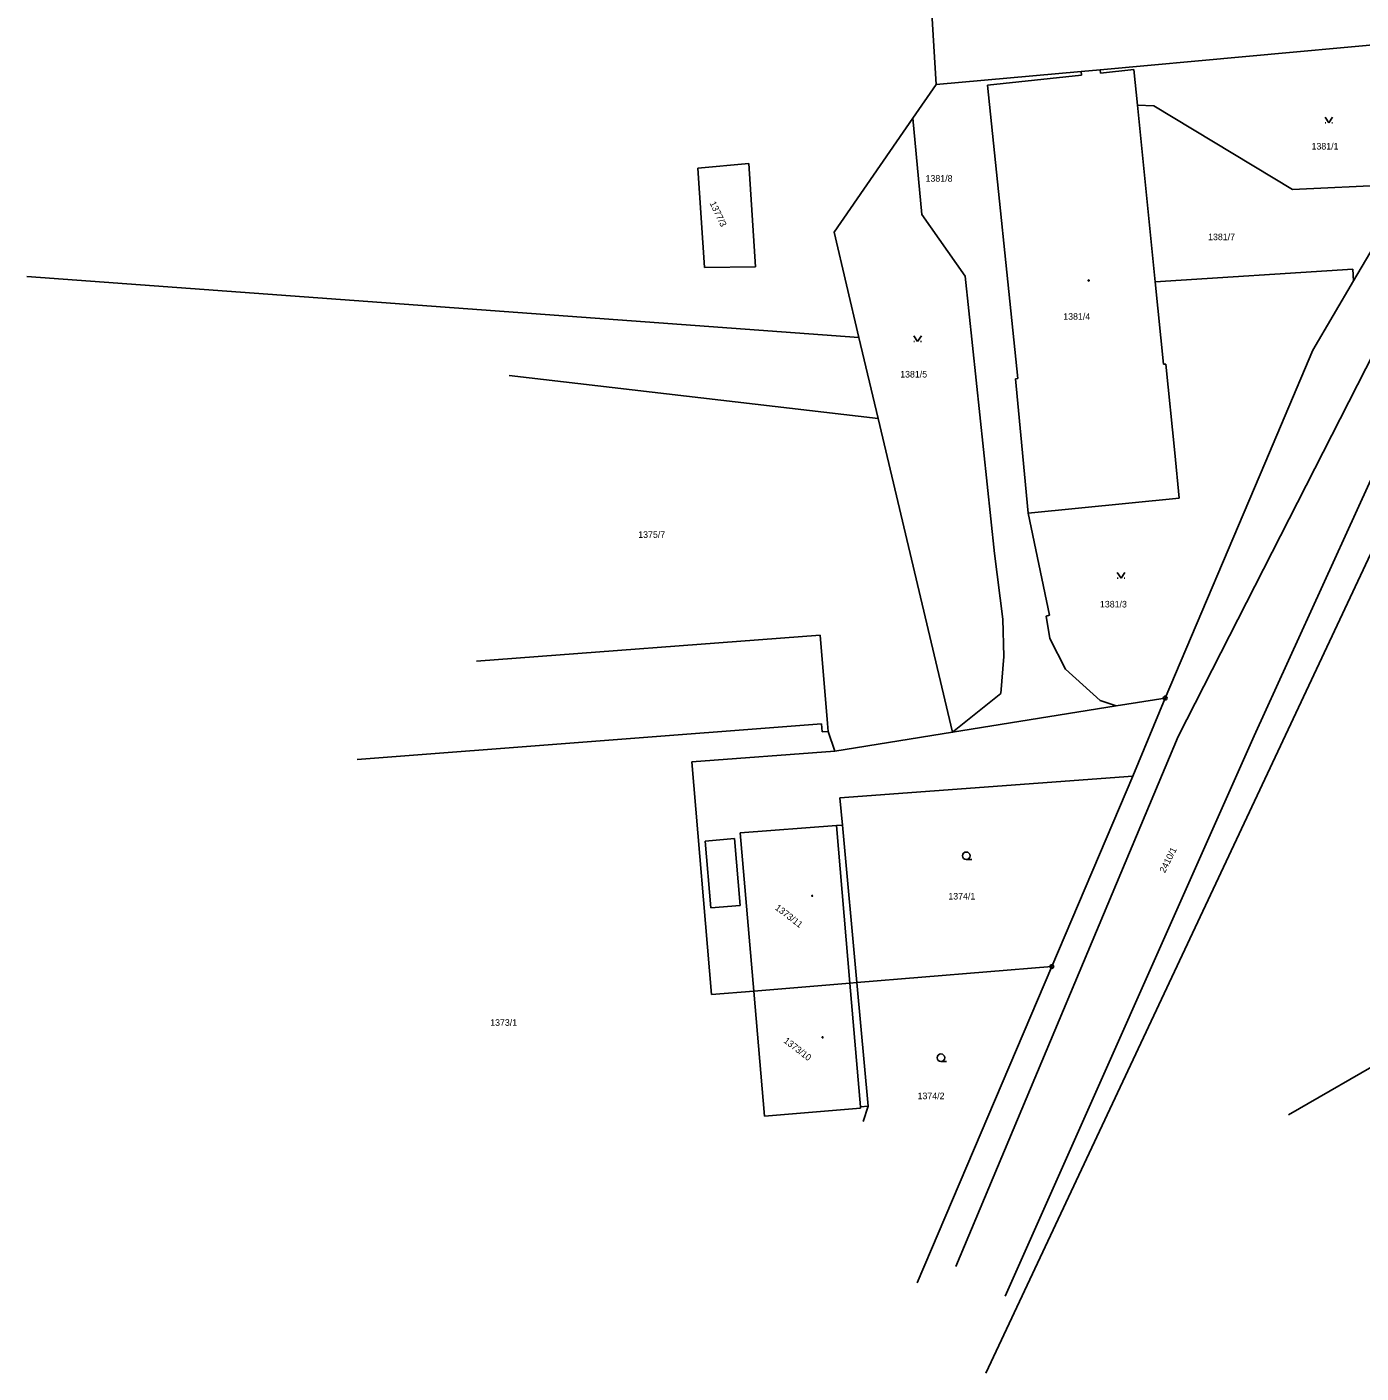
# Model space of a CAD drawing. Extents: x -454285 to -453563, y -1108687 to -1108249.
# Drawn here: x -454283.2 to -454141.3, y -1108686.8 to -1108543.6 of the extents above; entities that cross this region are included whole.
import ezdxf

# ---------------------------------------------------------------- set-up
doc = ezdxf.new("R2010")
doc.units = 0
for name, color, linetype in [('1', 7, 'Continuous'), ('14', 7, 'Continuous'), ('15', 7, 'Continuous'), ('16', 7, 'Continuous'), ('2', 7, 'Continuous'), ('23', 7, 'Continuous'), ('25', 7, 'Continuous'), ('28', 7, 'Continuous')]:
    doc.layers.add(name, color=color, linetype=linetype)

# ---------------------------------------------------------------- blocks, each defined once
blk = doc.blocks.new('Z402')
for start, end in [(0, 180), (180, 0)]:
    blk.add_arc((0, 0), 0.15, start, end)
blk = doc.blocks.new('Z105')
for radius in [0.5, 0.01]:
    blk.add_circle((0, 0), radius)
blk = doc.blocks.new('Z3140')
for p, q in [((-1, 1.5), (0, 0)), ((-1, 0), (-0.8, 0)), ((0, 0), (1, 1.5)), ((0.8, 0), (1, 0))]:
    blk.add_line(p, q)
blk = doc.blocks.new('Z3040')
blk.add_line((1.5, 0), (0, 0))
blk.add_circle((0, 1), 1)

msp = doc.modelspace()

# ---------------------------------------------------------------- linework, layer by layer
at = {"layer": '1'}
for p, q in [((-454188.53, -1108516.12), (-454186.51, -1108549.78)), ((-454169.07, -1108548.2), (-454133.68, -1108544.98)), ((-454186.51, -1108549.78), (-454171.1, -1108548.38)), ((-454181.06, -1108549.84), (-454171.06, -1108548.77)), ((-454171.1, -1108548.38), (-454169.07, -1108548.2)), ((-454171.06, -1108548.77), (-454171.1, -1108548.38)), ((-454169.07, -1108548.2), (-454169.03, -1108548.56)), ((-454169.03, -1108548.56), (-454165.48, -1108548.18)), ((-454165.48, -1108548.18), (-454165.1, -1108551.96)), ((-454188.97, -1108553.33), (-454186.51, -1108549.78)), ((-454177.83, -1108581.04), (-454181.06, -1108549.84)), ((-454163.21, -1108570.75), (-454165.1, -1108551.96)), ((-454165.1, -1108551.96), (-454163.37, -1108552.02)), ((-454163.37, -1108552.02), (-454148.61, -1108560.94)), ((-454197.36, -1108565.46), (-454188.97, -1108553.33)), ((-454188.97, -1108553.33), (-454188.04, -1108563.6)), ((-454211.84, -1108558.67), (-454206.42, -1108558.16)), ((-454211.15, -1108569.21), (-454211.84, -1108558.67)), ((-454206.42, -1108558.16), (-454205.73, -1108569.15)), ((-454148.61, -1108560.94), (-454136.08, -1108560.35)), ((-454136.08, -1108560.35), (-454142.12, -1108570.65)), ((-454149.03, -1108659.33), (-453980.37, -1108561.48)), ((-454188.04, -1108563.6), (-454183.42, -1108570.14)), ((-454194.71, -1108576.65), (-454197.36, -1108565.46)), ((-454283.18, -1108570.17), (-454194.71, -1108576.65)), ((-454205.73, -1108569.15), (-454211.15, -1108569.21)), ((-454180.29, -1108599.62), (-454183.42, -1108570.14)), ((-454142.21, -1108569.4), (-454163.21, -1108570.75)), ((-454142.12, -1108570.65), (-454142.21, -1108569.4)), ((-454163.21, -1108570.75), (-454162.33, -1108579.51)), ((-454142.12, -1108570.65), (-454146.45, -1108578.02)), ((-454194.71, -1108576.65), (-454192.67, -1108585.28)), ((-454146.45, -1108578.02), (-454151.56, -1108590.05)), ((-454130.67, -1108579.12), (-454181.21, -1108686.77)), ((-454162.33, -1108579.51), (-454162.08, -1108579.49)), ((-454161.13, -1108588.94), (-454162.08, -1108579.49)), ((-454192.67, -1108585.28), (-454231.91, -1108580.71)), ((-454178.08, -1108581.06), (-454177.83, -1108581.04)), ((-454178.08, -1108581.06), (-454177.51, -1108587.04)), ((-454192.67, -1108585.28), (-454184.78, -1108618.64)), ((-454177.51, -1108587.04), (-454176.72, -1108595.36)), ((-454161.13, -1108588.94), (-454160.65, -1108593.75)), ((-454151.56, -1108590.05), (-454162.16, -1108615)), ((-454176.72, -1108595.36), (-454160.65, -1108593.75)), ((-454176.72, -1108595.36), (-454174.46, -1108606.19)), ((-454180.29, -1108599.62), (-454179.4, -1108606.6)), ((-454179.4, -1108606.6), (-454179.3, -1108610.58)), ((-454174.46, -1108606.19), (-454174.8, -1108606.3)), ((-454174.8, -1108606.3), (-454174.43, -1108608.68)), ((-454235.39, -1108611.07), (-454198.85, -1108608.3)), ((-454198.85, -1108608.3), (-454198.07, -1108617.69)), ((-454174.43, -1108608.68), (-454172.76, -1108611.92)), ((-454179.3, -1108610.58), (-454179.64, -1108614.53)), ((-454172.76, -1108611.92), (-454169.08, -1108615.25)), ((-454179.64, -1108614.53), (-454184.78, -1108618.64)), ((-454167.35, -1108615.84), (-454184.78, -1108618.64)), ((-454169.08, -1108615.25), (-454167.35, -1108615.84)), ((-454167.35, -1108615.84), (-454162.16, -1108615)), ((-454165.6, -1108623.31), (-454162.16, -1108615)), ((-454198.68, -1108617.74), (-454248.06, -1108621.52)), ((-454198.68, -1108617.74), (-454198.62, -1108618.61)), ((-454198.62, -1108618.61), (-454198, -1108618.56)), ((-454198, -1108618.56), (-454198.07, -1108617.69)), ((-454198, -1108618.56), (-454197.29, -1108620.65)), ((-454184.78, -1108618.64), (-454197.29, -1108620.65)), ((-454165.6, -1108623.31), (-454196.76, -1108625.61)), ((-454174.21, -1108643.55), (-454165.6, -1108623.31)), ((-454196.76, -1108625.61), (-454196.45, -1108628.5)), ((-454207.33, -1108629.32), (-454197.1, -1108628.56)), ((-454196.45, -1108628.5), (-454197.1, -1108628.56)), ((-454195.68, -1108645.32), (-454197.1, -1108628.56)), ((-454207.33, -1108629.32), (-454205.89, -1108646.16)), ((-454194.93, -1108645.26), (-454174.21, -1108643.55)), ((-454174.21, -1108643.55), (-454188.53, -1108677.19)), ((-454205.89, -1108646.16), (-454195.68, -1108645.32)), ((-454205.89, -1108646.16), (-454204.76, -1108659.47)), ((-454195.68, -1108645.32), (-454194.93, -1108645.26)), ((-454194.56, -1108658.46), (-454195.68, -1108645.32)), ((-454194.55, -1108658.62), (-454204.76, -1108659.47)), ((-454193.74, -1108658.4), (-454194.56, -1108658.46)), ((-454194.56, -1108658.46), (-454194.55, -1108658.62)), ((-454194.25, -1108660.01), (-454193.74, -1108658.4))]:
    msp.add_line(p, q, dxfattribs=at)
at = {"layer": '2'}
for p, q in [((-454160.76, -1108619.1), (-454130.24, -1108559.15)), ((-454133.45, -1108576.74), (-454152.68, -1108619.03)), ((-454152.68, -1108619.03), (-454179.15, -1108678.59)), ((-454184.43, -1108675.44), (-454160.76, -1108619.1)), ((-454197.29, -1108620.65), (-454212.49, -1108621.78)), ((-454212.49, -1108621.78), (-454210.38, -1108646.53)), ((-454196.45, -1108628.5), (-454194.93, -1108645.26)), ((-454211.07, -1108630.2), (-454207.96, -1108629.93)), ((-454210.46, -1108637.32), (-454211.07, -1108630.2)), ((-454207.96, -1108629.93), (-454207.35, -1108637.06)), ((-454207.35, -1108637.06), (-454210.46, -1108637.32)), ((-454210.38, -1108646.53), (-454205.89, -1108646.16)), ((-454194.93, -1108645.26), (-454193.74, -1108658.4))]:
    msp.add_line(p, q, dxfattribs=at)

# ---------------------------------------------------------------- block references
at = {"layer": '23', "xscale": 0.4, "yscale": 0.4000000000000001}
for name, p in [('Z3140', (-454144.75, -1108553.84)), ('Z3140', (-454188.48, -1108577.09)), ('Z3140', (-454166.85, -1108602.26)), ('Z3040', (-454183.3, -1108632.17)), ('Z3040', (-454186, -1108653.64))]:
    msp.add_blockref(name, p, dxfattribs=at)
at = {"layer": '25', "xscale": 0.4, "yscale": 0.4000000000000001}
for p in [(-454170.29, -1108570.6), (-454199.68, -1108636.03), (-454198.58, -1108651.07)]:
    msp.add_blockref('Z402', p, dxfattribs=at)
at = {"layer": '28', "xscale": 0.4, "yscale": 0.4000000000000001}
for p in [(-454162.16, -1108615), (-454174.21, -1108643.55)]:
    msp.add_blockref('Z105', p, dxfattribs=at)

# ---------------------------------------------------------------- texts
at = {"layer": '14'}
for s, p in [('1381/1', (-454146.59, -1108556.68)), ('1381/8', (-454187.63, -1108560.1)), ('1381/7', (-454157.59, -1108566.32)), ('1381/5', (-454190.33, -1108580.92)), ('1375/7', (-454218.18, -1108597.97)), ('1381/3', (-454169.09, -1108605.37)), ('1374/1', (-454185.21, -1108636.42)), ('1373/1', (-454233.92, -1108649.85)), ('1374/2', (-454188.48, -1108657.65))]:
    msp.add_text(s, height=0.7, dxfattribs=at).set_placement(p)
msp.add_text('1377/3', height=0.7, rotation=295.533, dxfattribs=at).set_placement((-454210.61, -1108562.39))
at = {"layer": '15'}
msp.add_text('1381/4', height=0.7, dxfattribs=at).set_placement((-454172.99, -1108574.78))
for s, p in [('1373/11', (-454203.7, -1108637.42)), ('1373/10', (-454202.79, -1108651.56))]:
    msp.add_text(s, height=0.7, rotation=322.407, dxfattribs=at).set_placement(p)
at = {"layer": '16'}
msp.add_text('2410/1', height=0.7, rotation=63.5082, dxfattribs=at).set_placement((-454162.18, -1108633.65))

doc.saveas('drawing.dxf')
